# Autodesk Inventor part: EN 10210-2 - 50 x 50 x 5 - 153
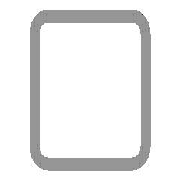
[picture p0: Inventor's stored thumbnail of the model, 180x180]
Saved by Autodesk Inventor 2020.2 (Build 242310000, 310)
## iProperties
IsCustomPart: 1
_CCFamilyMember: 16
_CCFamilyDisplayName: DIN EN 10210-2 (USAS B17.1 quadratisch) - Rohrleitung — In Klammern angegebene Größen wurden aufgehoben
_FrameMemberDoc: Frame Member File
_Version: 15.0.0
_GetPNFromCC: 1
Created: 2019-01
Part Number: EN 10210-2 - 50 x 50 x 5 - 153
Material: Stahl, weich
Description: Rohrleitung
Document SubType Name: Modeling
Standard: DIN
Designer: lutzd
Standard Revision: 2006-07
Standards Organization: DIN
Language: de-DE
Size Designation: 50 x 50 x 5
Categories: <MemberInstance><Categories><Category DisplayName="Profile" InternalName="089c4875-fa83-4c05-b084-43b9cc11f5ed" Mnemonic="GRDR"><CategoryParameter DisplayName="
Stock Number: 50 x 50 x 5
Mass: 1048.73 g
Surface Area: 535.429 cm^2
Volume: 133.596 cm^3
Density: 7.85 g/cm^3
Appearance: Semi-Polished(8)
G_L: 153,000 mm
G_W: 50,000 mm
G_H: 50,000 mm
DocNumber: ADSK-014281
Folder: .
Dimensions: 50x50x153 mm
Mass: 1,049 kg
+6CA9C4A1-E230-42E1-BD5D-672BDE29552E+SCHNITTDETAIL1: Schnittwinkel 90,00 grd
+04059DC8-4BB0-4C69-94E8-B8101AD5D12B+SCHNITTDETAIL2: Schnittwinkel 90,00 grd
VLT_Material: Stahl, weich
Title: Profil-Bauteil
Author: lutzd
Revision Number: -
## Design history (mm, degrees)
node "Startebene"
node "Endebene"
sketch "Skizze"
  geometry: L1 (-25, -17.5)-(-25, 17.5); L2 (-17.5, 25)-(17.5, 25); L3 (25, 17.5)-(25, -17.5); L4 (17.5, -25)-(-17.5, -25); L5 (-15, 20)-(15, 20); L6 (20, 15)-(20, -15); L7 (15, -20)-(-15, -20); L8 (-20, -15)-(-20, 15); L9 (0, 37.175)-(0, -37.175) reference; L10 (-37.175, 0)-(37.175, 0) reference; A1 r 7.5 centre (-17.5, -17.5) between (-25, -17.5) and (-17.5, -25); A2 r 7.5 centre (-17.5, 17.5) between (-17.5, 25) and (-25, 17.5); A3 r 7.5 centre (17.5, 17.5) between (25, 17.5) and (17.5, 25); A4 r 7.5 centre (17.5, -17.5) between (17.5, -25) and (25, -17.5); A5 r 5 centre (-15, -15) between (-20, -15) and (-15, -20); A6 r 5 centre (-15, 15) between (-15, 20) and (-20, 15); A7 r 5 centre (15, 15) between (20, 15) and (15, 20); A8 r 5 centre (15, -15) between (15, -20) and (20, -15)
  constraints: 16 end point, 16 point on circle, 16 tangent, 8 centre point, 6 equal radius, 4 parallel, 2 perpendicular, 2 other
  dimensions: "d7" = 7.5 radius of A1 (= G_IR); "d10" = 50 distance between parallel lines of L2 L4 (= G_H); "d11" = 50 distance between parallel lines of L1 L3 (= G_W); "d12" = 5 distance between parallel lines of L3 L6 (= G_T); "d15" = 25 distance between parallel lines of L2 L10 (= 0.5 x d10); "d16" = 25 distance between parallel lines of L9 L3 (= 0.5 x d11); "d19" = 5 radius of A5 (= G_T); "d20" = 5 distance between parallel lines of L4 L7 (= G_T)
extrude "Körper" new body sketch "Skizze" stored distance "d3" = 153 (= G_L); taper "d4" = 0 deg
node "Driven Length"
  sketch "Sketch3"
    geometry: L1 (0, 0)-(10, 0) reference
    constraints: 2 end point, 1 horizontal
  workplane "Work Plane3"
  sketch "Sketch4"
    geometry: L1 (-2, 50)-(12, 50) reference; L2 (-2, 203)-(12, 203) reference
    dimensions: "d18" = 153 distance between parallel lines of L1 L2 (derived)
workplane "Arbeitsebene4"
feature "Trennen1"
workplane "Arbeitsebene5"
feature "Trennen2"
body "Solid1"
other parameters: "G_W" = 50 [user parameter; used in 1 equation term], "G_H" = 50 [user parameter; used in 1 equation term], "G_T" = 5 [user parameter; used in 3 equation terms], "G_IR" = 7.5 [user parameter; used in 1 equation term], "G_L" = 153 (= d18) [user parameter; used in 1 equation term], "d14" = 203 (= G_OFFSET_END + B_L), "B_L" = 253 [user parameter; used in 1 equation term], "d17" = 90 deg
